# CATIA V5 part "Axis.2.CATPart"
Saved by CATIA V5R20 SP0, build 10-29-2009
Part number: Axis.2
Publications: "点.10", "直線.28", "直線.29", "直線.30"
Bounding box of the stored display mesh (mm): x 8.677 to 41.323, y -64.142 to -35.858, z 20.858 to 49.142
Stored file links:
  C:\Work\#01 CATIA Lecture Materials\#299 TOYOTA CATIA V5\TOYOTA_CATIA\LCS\Surface\Surface EX02\Axis.2.CATPart
  Product1.CATProduct
  Part1.CATPart
  C:\Work\#01 CATIA Lecture Materials\#299 TOYOTA CATIA V5\TOYOTA_CATIA\Surface\Surface.3\Axis.1.CATPart
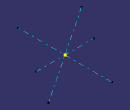
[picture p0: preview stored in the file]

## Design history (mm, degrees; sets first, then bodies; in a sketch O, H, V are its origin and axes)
Set1 "Axis"
  Point1: stored without definition
  Line1 to Line3: stored without definition
Body1 (main body)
